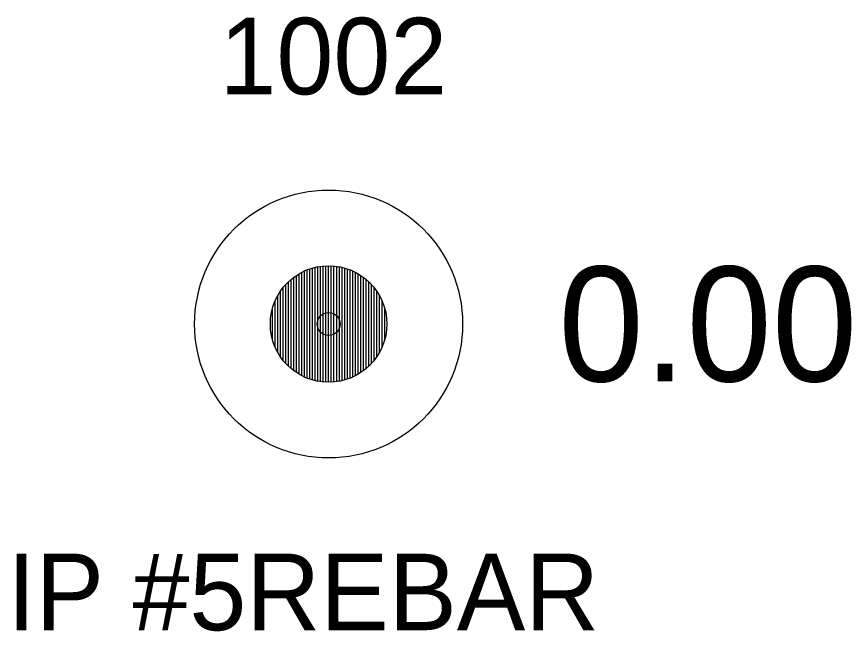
# Model space of a CAD drawing. Extents: x 2274993 to 2278766, y 1075634 to 1076749.
# Drawn here: x 2278643.33 to 2278654.23, y 1076741.03 to 1076749.06 of the extents above; entities that cross this region are included whole.
import ezdxf

# ---------------------------------------------------------------- set-up
doc = ezdxf.new("R2010")
doc.units = 0
for name, color, linetype in [('RD_EX_DV_Prop_txCode', 7, 'Continuous'), ('RD_EX_DV_PropPin', 7, 'Continuous'), ('RD_EX_TX_DV_Prop_ELEV', 7, 'Continuous'), ('RD_SMD_Locator', 7, 'Continuous')]:
    doc.layers.add(name, color=color, linetype=linetype)

msp = doc.modelspace()

# ---------------------------------------------------------------- linework, layer by layer
at = {"layer": 'RD_EX_DV_PropPin'}
for p, q in [((2278647.16, 1076744.321), (2278647.16, 1076745.762)), ((2278647.195, 1076744.31), (2278647.195, 1076745.773)), ((2278647.23, 1076744.301), (2278647.23, 1076745.782)), ((2278647.265, 1076744.294), (2278647.265, 1076745.79)), ((2278647.3, 1076744.288), (2278647.3, 1076745.795)), ((2278647.335, 1076744.284), (2278647.335, 1076745.799)), ((2278647.37, 1076744.281), (2278647.37, 1076745.802)), ((2278647.405, 1076744.281), (2278647.405, 1076745.803)), ((2278647.44, 1076744.281), (2278647.44, 1076745.802)), ((2278647.475, 1076744.284), (2278647.475, 1076745.799)), ((2278647.51, 1076744.288), (2278647.51, 1076745.795)), ((2278647.545, 1076744.294), (2278647.545, 1076745.79)), ((2278647.58, 1076744.301), (2278647.58, 1076745.782)), ((2278647.615, 1076744.31), (2278647.615, 1076745.773)), ((2278647.65, 1076744.321), (2278647.65, 1076745.762)), ((2278646.95, 1076744.432), (2278646.95, 1076745.652)), ((2278646.985, 1076744.407), (2278646.985, 1076745.676)), ((2278647.02, 1076744.385), (2278647.02, 1076745.698)), ((2278647.055, 1076744.366), (2278647.055, 1076745.717)), ((2278647.09, 1076744.349), (2278647.09, 1076745.734)), ((2278647.125, 1076744.334), (2278647.125, 1076745.749)), ((2278647.685, 1076744.334), (2278647.685, 1076745.749)), ((2278647.72, 1076744.349), (2278647.72, 1076745.734)), ((2278647.755, 1076744.366), (2278647.755, 1076745.717)), ((2278647.79, 1076744.385), (2278647.79, 1076745.698)), ((2278647.825, 1076744.407), (2278647.825, 1076745.676)), ((2278647.86, 1076744.432), (2278647.86, 1076745.652)), ((2278646.845, 1076744.527), (2278646.845, 1076745.557)), ((2278646.88, 1076744.491), (2278646.88, 1076745.592)), ((2278646.915, 1076744.46), (2278646.915, 1076745.624)), ((2278647.895, 1076744.46), (2278647.895, 1076745.624)), ((2278647.93, 1076744.491), (2278647.93, 1076745.592)), ((2278647.965, 1076744.527), (2278647.965, 1076745.557)), ((2278646.775, 1076744.615), (2278646.775, 1076745.468)), ((2278646.81, 1076744.568), (2278646.81, 1076745.516)), ((2278648, 1076744.568), (2278648, 1076745.516)), ((2278648.035, 1076744.615), (2278648.035, 1076745.468)), ((2278646.705, 1076744.744), (2278646.705, 1076745.34)), ((2278646.74, 1076744.672), (2278646.74, 1076745.411)), ((2278648.07, 1076744.672), (2278648.07, 1076745.411)), ((2278648.105, 1076744.744), (2278648.105, 1076745.34)), ((2278646.67, 1076744.846), (2278646.67, 1076745.238)), ((2278648.14, 1076744.846), (2278648.14, 1076745.238))]:
    msp.add_line(p, q, dxfattribs=at)
for radius in [1.75, 0.761]:
    msp.add_circle((2278647.405, 1076745.042), radius, dxfattribs=at)
at = {"layer": 'RD_SMD_Locator'}
msp.add_circle((2278647.405, 1076745.042), 0.15, dxfattribs=at)

# ---------------------------------------------------------------- texts
at = {"layer": 'RD_EX_DV_Prop_txCode'}
for s, p in [('1002', (2278645.98, 1076748.042)), ('IP #5REBAR', (2278643.208, 1076741.042))]:
    msp.add_text(s, height=1, dxfattribs=at).set_placement(p)
at = {"layer": 'RD_EX_TX_DV_Prop_ELEV'}
msp.add_text('0.00', height=1.5, dxfattribs=at).set_placement((2278650.405, 1076744.292))

doc.saveas('drawing.dxf')
